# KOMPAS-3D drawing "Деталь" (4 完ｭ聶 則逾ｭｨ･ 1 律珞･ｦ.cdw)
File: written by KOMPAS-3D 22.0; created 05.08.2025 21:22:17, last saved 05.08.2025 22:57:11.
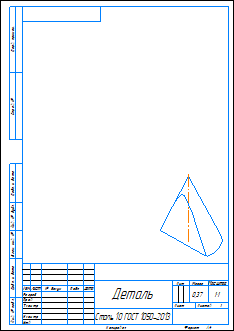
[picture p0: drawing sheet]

Sheet 1: A4, portrait

Document properties: Автор: user; Масса: 0.373939; Полное имя файла: G:\08 05 вторник\2025 НГ Лаб работы\Лаб 4 Сечение конуса\4 Чертежи\4 Конус Сечение 1 Чертеж.cdw

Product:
- Part/product: Деталь
    Масса: 0.373939

Title block, sheet 1: Наименование: Деталь; Материал: Сталь 10 ГОСТ 1050-2013; Масса: 0,37; Количество листов документа: 1; Форматы листов документа: A4; stored path: G:\08 05 вторник\2025 НГ Лаб работы\Лаб 4 Сечение конуса\4 Чертежи\4 Конус Сечение 3 Чертеж.cdw

Views: Изометрия 2
Dimensions and other numbers on the sheet: 1:1; 1; 0,37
